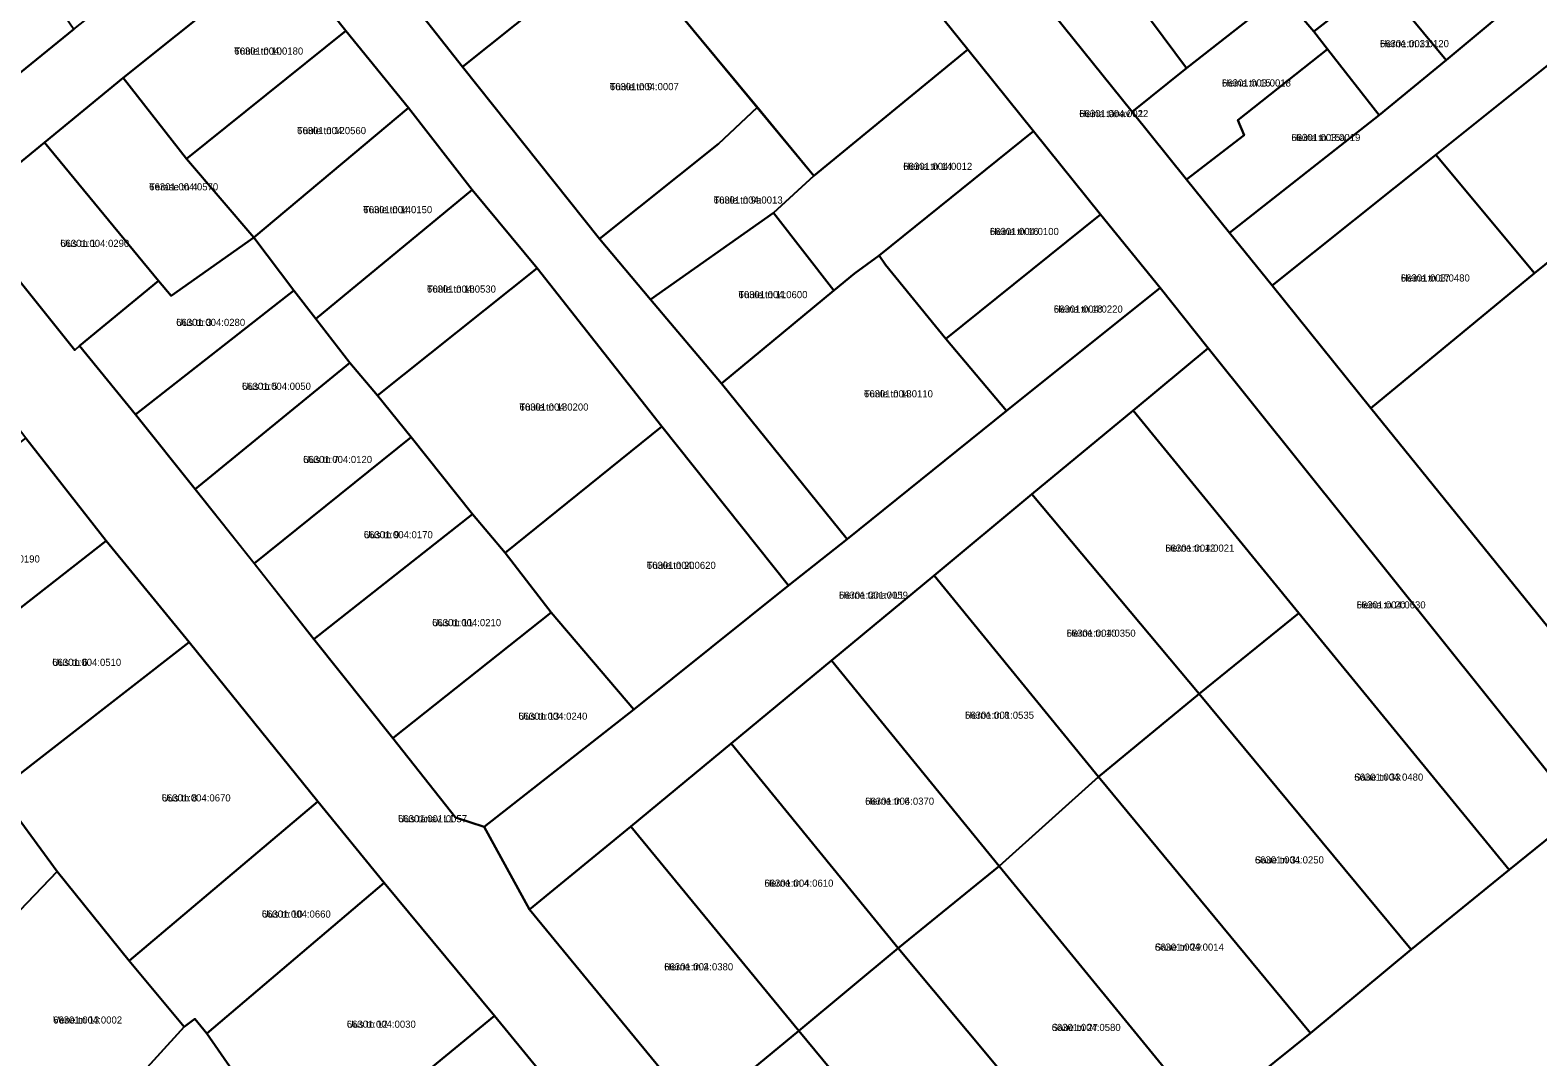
# Model space of a CAD drawing. Extents: x 632278 to 636344, y 6578401 to 6583362.
# Drawn here: x 634644.7 to 634961.7, y 6581724.1 to 6581940 of the extents above; entities that cross this region are included whole.
import ezdxf

# ---------------------------------------------------------------- set-up
doc = ezdxf.new("R2010")
doc.units = 0
for name, color, linetype in [('L_AADRESS', 7, 'Continuous'), ('PIIR', 7, 'Continuous'), ('TUNNUS', 7, 'Continuous')]:
    doc.layers.add(name, color=color, linetype=linetype)

msp = doc.modelspace()

# ---------------------------------------------------------------- linework, layer by layer
at = {"layer": 'PIIR'}
for points in [[(634940.19, 6581913.77), (634905.84, 6581886.27), (634896.84, 6581897.33), (634928.28, 6581922.11), (634942.36, 6581933.66), (634961.4, 6581949.58), (634972.37, 6581958.24), (635006.62, 6581985.9), (635015.11, 6581992.73), (635039.39, 6582012.29), (635051.5, 6582021.93), (635101.21, 6582062.86), (635112.93, 6582072.11), (635121.55, 6582060.43), (635093, 6582037.1), (635059.67, 6582010.01), (635048.56, 6582001.14), (635015.04, 6581973.94), (634981.54, 6581946.7), (634970.74, 6581938.17)], [(634657.44, 6582006.52), (634652.83, 6582010.24), (634603.94, 6582047.53), (634613.71, 6582058.49), (634665.06, 6582018.52), (634699.64, 6581977.29), (634708.82, 6581965.62), (634721.78, 6581949.85), (634735.56, 6581932.26), (634764.41, 6581896.09), (634775.13, 6581883.33), (634790.02, 6581865.68), (634816.43, 6581832.94), (634804.08, 6581823.17), (634777.49, 6581856.65), (634751.26, 6581889.92), (634737.61, 6581906.43), (634724.24, 6581923.68), (634711.06, 6581939.81), (634697.67, 6581956.75), (634688.59, 6581967.7), (634680.6, 6581977.83), (634660.03, 6582003.65)], [(634907.8, 6581947.66), (634887.13, 6581972.74), (634921.03, 6581999.88), (634947.9, 6581966.83), (634928.46, 6581950.54), (634914.58, 6581939.67)], [(634856.74, 6581961.32), (634849.69, 6581956.01), (634847.46, 6581958.76), (634878.6, 6581983.47), (634887.13, 6581972.74), (634907.8, 6581947.66), (634887.8, 6581932.02), (634865.94, 6581961.44)], [(634623.36, 6581979.36), (634646.78, 6581950.66), (634653.84, 6581940.16), (634630.24, 6581921.06), (634619.09, 6581933.95), (634597.79, 6581962.1)], [(634809.42, 6581909.34), (634798.35, 6581922.81), (634779.03, 6581946.06), (634811.99, 6581972.97), (634841.83, 6581935.93)], [(634545.08, 6581829.55), (634540.35, 6581834.86), (634549.04, 6581843.17), (634568.29, 6581865.93), (634565.82, 6581869.29), (634576.69, 6581877.91), (634583.39, 6581883.14), (634605.36, 6581901.38), (634630.24, 6581921.06), (634653.84, 6581940.16), (634688.59, 6581967.7), (634697.67, 6581956.75), (634664.21, 6581929.96), (634647.68, 6581916.34), (634630.37, 6581902.21), (634615.84, 6581890.6), (634577.32, 6581859.75), (634571.61, 6581855.04), (634560.16, 6581846.09)], [(634928.46, 6581950.54), (634947.9, 6581966.83), (634961.4, 6581949.58), (634942.36, 6581933.66)], [(634721.78, 6581949.85), (634738.82, 6581962.78), (634752.19, 6581945.49), (634735.56, 6581932.26)], [(634856.74, 6581961.32), (634865.94, 6581961.44), (634887.8, 6581932.02), (634876.36, 6581922.83), (634849.69, 6581956.01)], [(634735.56, 6581932.26), (634752.19, 6581945.49), (634768.66, 6581958.6), (634779.03, 6581946.06), (634797.54, 6581923.69), (634789.37, 6581916.09), (634764.41, 6581896.09)], [(634677.53, 6581912.93), (634664.21, 6581929.96), (634697.67, 6581956.75), (634711.06, 6581939.81)], [(634914.58, 6581939.67), (634928.46, 6581950.54), (634942.36, 6581933.66), (634928.28, 6581922.11), (634917.45, 6581935.99)], [(634907.8, 6581947.66), (634914.58, 6581939.67), (634917.45, 6581935.99), (634898.6, 6581921.06), (634899.93, 6581917.87), (634887.78, 6581908.61), (634876.36, 6581922.83), (634887.8, 6581932.02)], [(634677.53, 6581912.93), (634711.06, 6581939.81), (634724.24, 6581923.68), (634691.72, 6581896.41)], [(634841.83, 6581935.93), (634855.6, 6581918.72), (634823.21, 6581892.57), (634817.96, 6581888.81), (634813.62, 6581885.25), (634800.98, 6581901.57), (634809.42, 6581909.34)], [(634917.45, 6581935.99), (634928.28, 6581922.11), (634896.84, 6581897.33), (634887.78, 6581908.61), (634899.93, 6581917.87), (634898.6, 6581921.06)], [(634970.74, 6581938.17), (634991.13, 6581913.2), (634960.95, 6581888.89), (634940.19, 6581913.77)], [(634664.21, 6581929.96), (634677.53, 6581912.93), (634691.72, 6581896.41), (634674.32, 6581884.12), (634671.64, 6581887.28), (634647.68, 6581916.34)], [(634700.09, 6581885.22), (634691.72, 6581896.41), (634724.24, 6581923.68), (634737.61, 6581906.43), (634704.71, 6581879.3)], [(634797.54, 6581923.69), (634809.42, 6581909.34), (634800.98, 6581901.57), (634775.13, 6581883.33), (634764.41, 6581896.09), (634789.37, 6581916.09)], [(634824.48, 6581890.66), (634823.21, 6581892.57), (634855.6, 6581918.72), (634869.7, 6581901.21), (634837.18, 6581875.07)], [(634647.68, 6581916.34), (634671.64, 6581887.28), (634655.05, 6581873.59), (634654.08, 6581872.66), (634630.37, 6581902.21)], [(634940.19, 6581913.77), (634960.95, 6581888.89), (634926.55, 6581860.48), (634905.84, 6581886.27)], [(634926.55, 6581860.48), (634960.95, 6581888.89), (634991.13, 6581913.2), (635024.39, 6581872.43), (635048.44, 6581842.97), (634979.24, 6581795.37)], [(634711.91, 6581870.05), (634704.71, 6581879.3), (634737.61, 6581906.43), (634751.26, 6581889.92), (634717.69, 6581863.15)], [(634775.13, 6581883.33), (634800.98, 6581901.57), (634813.62, 6581885.25), (634790.02, 6581865.68)], [(634837.18, 6581875.07), (634869.7, 6581901.21), (634882.24, 6581885.76), (634849.96, 6581859.94)], [(634655.05, 6581873.59), (634671.64, 6581887.28), (634674.32, 6581884.12), (634691.72, 6581896.41), (634700.09, 6581885.22), (634666.85, 6581859.15)], [(634816.43, 6581832.94), (634790.02, 6581865.68), (634813.62, 6581885.25), (634817.96, 6581888.81), (634823.21, 6581892.57), (634824.48, 6581890.66), (634837.18, 6581875.07), (634849.96, 6581859.94)], [(634751.26, 6581889.92), (634777.49, 6581856.65), (634744.56, 6581830.03), (634737.69, 6581838.17), (634724.79, 6581854.37), (634717.69, 6581863.15)], [(634666.85, 6581859.15), (634700.09, 6581885.22), (634704.71, 6581879.3), (634711.91, 6581870.05), (634679.37, 6581843.47)], [(634749.69, 6581755.05), (634740.15, 6581772.43), (634771.6, 6581797.12), (634804.08, 6581823.17), (634816.43, 6581832.94), (634849.96, 6581859.94), (634882.24, 6581885.76), (634892.38, 6581873.11), (634876.57, 6581859.99), (634855.28, 6581842.42), (634834.73, 6581825.3), (634813.16, 6581807.39), (634792.03, 6581789.99), (634770.93, 6581772.51)], [(634876.57, 6581859.99), (634892.38, 6581873.11), (634970.56, 6581775.48), (634955.67, 6581763.37), (634911.42, 6581817.41)], [(634717.69, 6581863.15), (634724.79, 6581854.37), (634691.79, 6581827.85), (634679.37, 6581843.47), (634711.91, 6581870.05)], [(634855.28, 6581842.42), (634876.57, 6581859.99), (634911.42, 6581817.41), (634890.47, 6581800.41)], [(634744.56, 6581830.03), (634777.49, 6581856.65), (634804.08, 6581823.17), (634771.6, 6581797.12), (634754.2, 6581817.5)], [(634609.27, 6581815.3), (634602.63, 6581822.71), (634643.79, 6581854.2), (634660.65, 6581832.58), (634621.3, 6581801.86)], [(634691.79, 6581827.85), (634724.79, 6581854.37), (634737.69, 6581838.17), (634704.31, 6581811.89)], [(634855.28, 6581842.42), (634890.47, 6581800.41), (634869.31, 6581782.94), (634834.73, 6581825.3)], [(634704.31, 6581811.89), (634737.69, 6581838.17), (634744.56, 6581830.03), (634754.2, 6581817.5), (634720.91, 6581791.1)], [(634624.02, 6581798.82), (634621.3, 6581801.86), (634660.65, 6581832.58), (634678.08, 6581811.3), (634637.89, 6581780)], [(634813.16, 6581807.39), (634834.73, 6581825.3), (634869.31, 6581782.94), (634848.44, 6581764.18)], [(634734.13, 6581774.41), (634720.91, 6581791.1), (634754.2, 6581817.5), (634771.6, 6581797.12), (634740.15, 6581772.43)], [(634911.42, 6581817.41), (634955.67, 6581763.37), (634935.05, 6581746.67), (634890.47, 6581800.41)], [(634650.36, 6581763.08), (634637.89, 6581780), (634678.08, 6581811.3), (634705.15, 6581777.74), (634665.49, 6581744.26)], [(634792.03, 6581789.99), (634813.16, 6581807.39), (634848.44, 6581764.18), (634827.18, 6581746.96)], [(634890.47, 6581800.41), (634935.05, 6581746.67), (634913.86, 6581729.07), (634869.31, 6581782.94)], [(634624.02, 6581798.82), (634637.89, 6581780), (634650.36, 6581763.08), (634621.98, 6581733.45), (634594.33, 6581767.23)], [(634792.03, 6581789.99), (634827.18, 6581746.96), (634806.28, 6581729.53), (634770.93, 6581772.51)], [(634869.31, 6581782.94), (634913.86, 6581729.07), (634891.71, 6581711.25), (634848.44, 6581764.18)], [(634679.26, 6581732.06), (634677.02, 6581730.35), (634665.49, 6581744.26), (634705.15, 6581777.74), (634719.07, 6581760.66), (634681.83, 6581728.97)], [(634785.04, 6581712), (634749.69, 6581755.05), (634770.93, 6581772.51), (634806.28, 6581729.53)], [(634650.36, 6581763.08), (634665.49, 6581744.26), (634677.02, 6581730.35), (634656.47, 6581707.77), (634649.14, 6581699.55), (634621.98, 6581733.45)], [(634848.44, 6581764.18), (634891.71, 6581711.25), (634871.06, 6581694.38), (634827.18, 6581746.96)], [(634719.07, 6581760.66), (634742.28, 6581732.68), (634702.14, 6581699.71), (634692.62, 6581713.41), (634681.83, 6581728.97)], [(634827.18, 6581746.96), (634871.06, 6581694.38), (634871.4, 6581693.99), (634850.19, 6581676.48), (634849.75, 6581677.02), (634806.28, 6581729.53)], [(634649.14, 6581699.55), (634656.47, 6581707.77), (634677.02, 6581730.35), (634679.26, 6581732.06), (634681.83, 6581728.97), (634692.62, 6581713.41), (634663.03, 6581682.08)], [(634702.14, 6581699.71), (634742.28, 6581732.68), (634755.08, 6581717.15), (634729.7, 6581696.29), (634714.75, 6581684)], [(634806.28, 6581729.53), (634849.75, 6581677.02), (634828.19, 6581659.44), (634785.04, 6581712)]]:
    msp.add_lwpolyline(points, close=True, dxfattribs=at)
for points in [[(634970.56, 6581775.48), (634892.38, 6581873.11), (634882.24, 6581885.76), (634869.7, 6581901.21), (634855.6, 6581918.72), (634841.83, 6581935.93), (634811.99, 6581972.97)], [(634849.69, 6581956.01), (634876.36, 6581922.83), (634887.78, 6581908.61), (634896.84, 6581897.33), (634905.84, 6581886.27), (634926.55, 6581860.48), (634979.24, 6581795.37)], [(634755.08, 6581717.15), (634742.28, 6581732.68), (634719.07, 6581760.66), (634705.15, 6581777.74), (634678.08, 6581811.31), (634660.64, 6581832.59), (634643.79, 6581854.2), (634615.84, 6581890.6), (634630.37, 6581902.21), (634654.08, 6581872.66), (634655.05, 6581873.59), (634666.85, 6581859.15), (634679.37, 6581843.48), (634691.79, 6581827.86), (634704.31, 6581811.89), (634720.9, 6581791.1), (634734.12, 6581774.42), (634740.15, 6581772.43), (634749.69, 6581755.05), (634785.04, 6581712.01)], [(634891.71, 6581711.25), (634913.86, 6581729.07), (634935.05, 6581746.67), (634955.67, 6581763.37), (634970.56, 6581775.48), (635010.04, 6581726.18), (635004.04, 6581679.37)]]:
    msp.add_lwpolyline(points, dxfattribs=at)

# ---------------------------------------------------------------- texts
at = {"layer": 'L_AADRESS'}
for s, p in [('Tuule tn 10', (634687.58, 6581934.84)), ('Herne tn 11', (634928.47, 6581936.4)), ('Heina tn 15', (634895.25, 6581928.13)), ('Tuule tn 9', (634766.55, 6581927.36)), ('Heina tänav L1', (634865.25, 6581921.69)), ('Tuule tn 12', (634700.79, 6581918.11)), ('Heina tn 15a', (634909.85, 6581916.66)), ('Heina tn 14', (634828.24, 6581910.59)), ('Terase tn 4', (634669.7, 6581906.29)), ('Tuule tn 9a', (634788.38, 6581903.51)), ('Tuule tn 14', (634714.7, 6581901.49)), ('Heina tn 16', (634846.45, 6581896.9)), ('Uus tn 1', (634651, 6581894.4)), ('Heina tn 17', (634932.86, 6581887.12)), ('Tuule tn 16', (634728.1, 6581884.79)), ('Tuule tn 11', (634793.6, 6581883.62)), ('Heina tn 18', (634859.89, 6581880.58)), ('Uus tn 3', (634675.37, 6581877.78)), ('Uus tn 5', (634689.2, 6581864.34)), ('Tuule tn 13', (634819.98, 6581862.76)), ('Tuule tn 18', (634747.56, 6581859.98)), ('Uus tn 7', (634702.06, 6581848.95)), ('Uus tn 9', (634714.82, 6581833.13)), ('Herne tn 12', (634883.35, 6581830.31)), ('Tuule tn 20', (634774.32, 6581826.69)), ('Herne tänav L1', (634814.73, 6581820.41)), ('Heina tn 20', (634923.57, 6581818.37)), ('Uus tn 11', (634729.19, 6581814.64)), ('Herne tn 10', (634862.6, 6581812.42)), ('Uus tn 6', (634649.31, 6581806.29)), ('Uus tn 13', (634747.32, 6581794.96)), ('Herne tn 8', (634841.23, 6581795.17)), ('Saue tn 33', (634923.07, 6581782.15)), ('Uus tn 8', (634672.32, 6581777.78)), ('Herne tn 6', (634820.23, 6581777.09)), ('Uus tänav L1', (634722.02, 6581773.4)), ('Saue tn 31', (634902.18, 6581764.74)), ('Herne tn 4', (634799.05, 6581759.85)), ('Uus tn 10', (634693.37, 6581753.35)), ('Saue tn 29', (634881.15, 6581746.4)), ('Herne tn 2', (634777.98, 6581742.26)), ('Vene tn 13', (634649.5, 6581731.07)), ('Uus tn 12', (634711.25, 6581730.19)), ('Saue tn 27', (634859.45, 6581729.51))]:
    msp.add_text(s, height=1.5, dxfattribs=at).set_placement(p)
at = {"layer": 'TUNNUS'}
for s, p in [('66301:004:0180', (634687.58, 6581934.84)), ('66301:003:0120', (634928.47, 6581936.4)), ('66301:003:0018', (634895.25, 6581928.13)), ('66301:004:0007', (634766.55, 6581927.36)), ('66301:004:0022', (634865.25, 6581921.69)), ('66301:004:0560', (634700.79, 6581918.11)), ('66301:003:0019', (634909.85, 6581916.66)), ('66301:004:0012', (634828.24, 6581910.59)), ('66301:004:0570', (634669.7, 6581906.29)), ('66301:004:0013', (634788.38, 6581903.51)), ('66301:004:0150', (634714.7, 6581901.49)), ('66301:004:0100', (634846.45, 6581896.9)), ('66301:004:0290', (634651, 6581894.4)), ('66301:003:0480', (634932.86, 6581887.12)), ('66301:004:0530', (634728.1, 6581884.79)), ('66301:004:0600', (634793.6, 6581883.62)), ('66301:004:0220', (634859.89, 6581880.58)), ('66301:004:0280', (634675.37, 6581877.78)), ('66301:004:0050', (634689.2, 6581864.34)), ('66301:004:0110', (634819.98, 6581862.76)), ('66301:004:0200', (634747.56, 6581859.98)), ('66301:004:0120', (634702.06, 6581848.95)), ('66301:004:0170', (634714.82, 6581833.13)), ('66301:004:0021', (634883.35, 6581830.31)), ('66301:004:0190', (634632.2, 6581828.03)), ('66301:004:0620', (634774.32, 6581826.69)), ('66301:001:0059', (634814.73, 6581820.41)), ('66301:004:0630', (634923.57, 6581818.37)), ('66301:004:0210', (634729.19, 6581814.64)), ('66301:004:0350', (634862.6, 6581812.42)), ('66301:004:0510', (634649.31, 6581806.29)), ('66301:004:0240', (634747.32, 6581794.96)), ('66301:001:0535', (634841.23, 6581795.17)), ('66301:004:0480', (634923.07, 6581782.15)), ('66301:004:0670', (634672.32, 6581777.78)), ('66301:004:0370', (634820.23, 6581777.09)), ('66301:001:0057', (634722.02, 6581773.4)), ('66301:004:0250', (634902.18, 6581764.74)), ('66301:004:0610', (634799.05, 6581759.85)), ('66301:004:0660', (634693.37, 6581753.35)), ('66301:004:0014', (634881.15, 6581746.4)), ('66301:004:0380', (634777.98, 6581742.26)), ('66301:004:0002', (634649.5, 6581731.07)), ('66301:004:0030', (634711.25, 6581730.19)), ('66301:004:0580', (634859.45, 6581729.51))]:
    msp.add_text(s, height=1.5, dxfattribs=at).set_placement(p)

doc.saveas('drawing.dxf')
